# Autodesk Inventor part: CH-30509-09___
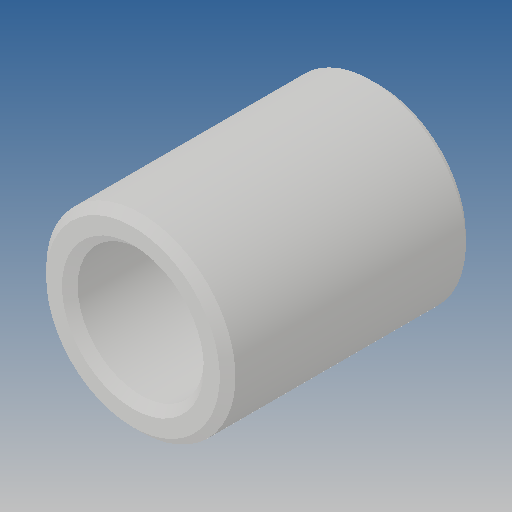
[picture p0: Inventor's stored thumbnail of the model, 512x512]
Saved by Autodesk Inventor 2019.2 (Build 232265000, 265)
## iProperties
Created: 2010-06
Part Number: CH-30509-09___
Material: Ogólny
Document SubType Name: Modeling
Designer: CADENGINEERING4
Density: 1 g/cm^3
Appearance: Domyślna
Author: CADENGINEERING4
Revision Number: ANY
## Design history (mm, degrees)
feature "NONE"
node "Bryła1"
